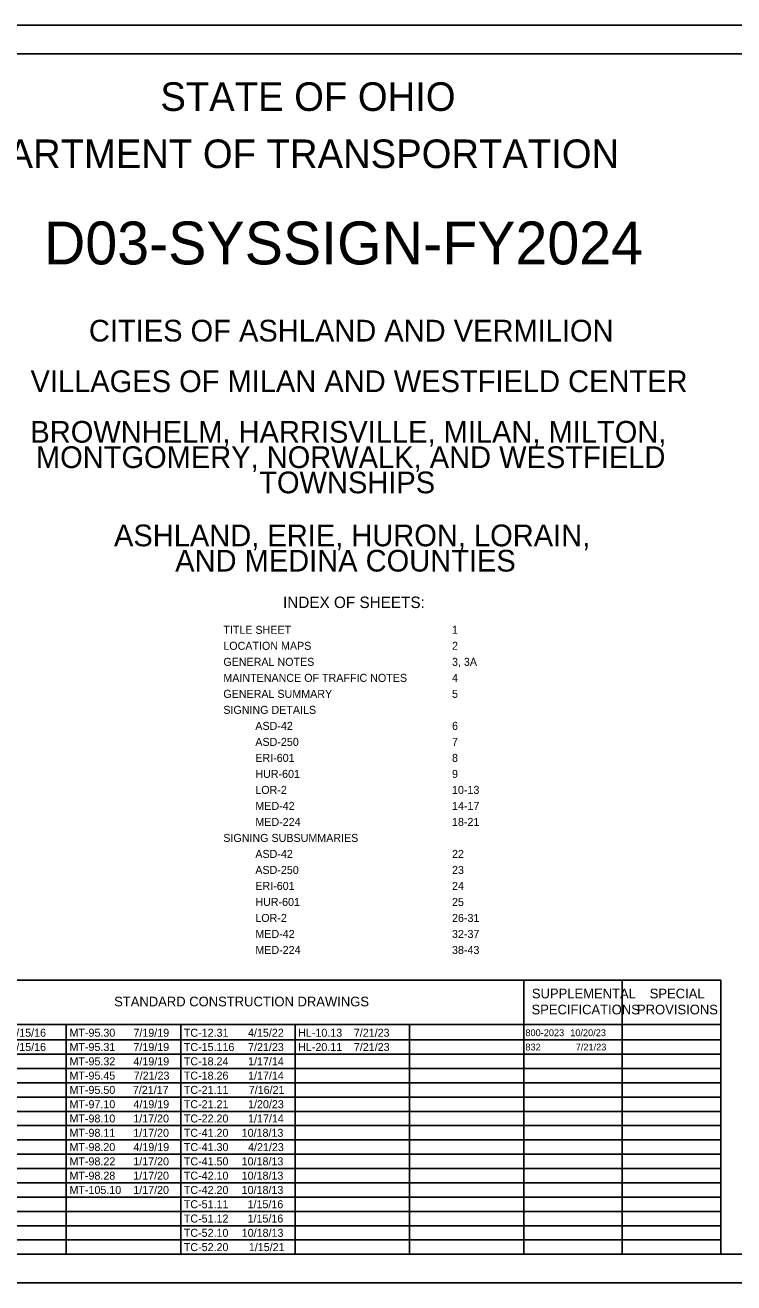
# Model space of a CAD drawing. Extents: x 0 to 34, y 0 to 22.
# Drawn here: x 11.43 to 23.83, y 0 to 22 of the extents above; entities that cross this region are included whole.
import ezdxf

# ---------------------------------------------------------------- set-up
doc = ezdxf.new("R2010")
doc.units = 0
for name, color, linetype in [('SH_Border', 7, 'Continuous'), ('SH_Cut_Line', 7, 'Continuous'), ('SH_Data', 7, 'Continuous'), ('SH_Text', 7, 'Continuous')]:
    doc.layers.add(name, color=color, linetype=linetype)

msp = doc.modelspace()

# ---------------------------------------------------------------- linework, layer by layer
at = {"layer": 'SH_Border'}
msp.add_lwpolyline([(1.5, 21.5), (33.5, 21.5), (33.5, 0.5), (1.5, 0.5)], close=True, dxfattribs=at)
at = {"layer": 'SH_Cut_Line'}
msp.add_lwpolyline([(0, 0), (34, 0), (34, 22), (0, 22)], close=True, dxfattribs=at)
at = {"layer": 'SH_Data'}
for p, q in [((10.15, 5.292), (23.6, 5.292)), ((20.15, 0.5), (20.15, 5.292)), ((21.875, 0.5), (21.875, 5.292)), ((23.6, 0.5), (23.6, 5.292)), ((10.15, 4.521), (23.6, 4.521)), ((12.15, 0.5), (12.15, 4.521)), ((14.15, 0.5), (14.15, 4.521)), ((16.15, 0.5), (16.15, 4.521)), ((18.15, 0.5), (18.15, 4.521)), ((10.15, 4.25), (23.6, 4.25)), ((10.15, 4), (23.6, 4)), ((10.15, 3.75), (23.6, 3.75)), ((10.15, 3.5), (23.6, 3.5)), ((10.15, 3.25), (23.6, 3.25)), ((10.15, 3), (23.6, 3)), ((10.15, 2.75), (23.6, 2.75)), ((10.15, 2.5), (23.6, 2.5)), ((10.15, 2.25), (23.6, 2.25)), ((10.15, 2), (23.6, 2)), ((10.15, 1.75), (23.6, 1.75)), ((10.15, 1.5), (23.6, 1.5)), ((10.15, 1.25), (23.6, 1.25)), ((10.15, 1), (23.6, 1)), ((10.15, 0.75), (23.6, 0.75))]:
    msp.add_line(p, q, dxfattribs=at)

# ---------------------------------------------------------------- texts
at = {"layer": 'SH_Text'}
for s, height, p in [('STATE OF OHIO', 0.5, (13.795, 20.5)), ('DEPARTMENT OF TRANSPORTATION', 0.5, (9.747, 19.5)), ('D03-SYSSIGN-FY2024', 0.75, (11.758, 17.815)), ('CITIES OF ASHLAND AND VERMILION', 0.38, (12.545, 16.466)), ('VILLAGES OF MILAN AND WESTFIELD CENTER', 0.38, (11.524, 15.581)), ('BROWNHELM, HARRISVILLE, MILAN, MILTON,', 0.38, (11.521, 14.696)), ('MONTGOMERY, NORWALK, AND WESTFIELD', 0.38, (11.618, 14.253)), ('TOWNSHIPS', 0.38, (15.524, 13.811)), ('ASHLAND, ERIE, HURON, LORAIN,', 0.38, (12.984, 12.884)), ('AND MEDINA COUNTIES', 0.38, (14.054, 12.442)), ('INDEX OF SHEETS:', 0.2, (15.94, 11.804)), ('TITLE SHEET', 0.14, (14.896, 11.353)), ('1', 0.14, (18.896, 11.353)), ('LOCATION MAPS', 0.14, (14.896, 11.073)), ('2', 0.14, (18.896, 11.073)), ('GENERAL NOTES', 0.14, (14.896, 10.793)), ('3, 3A', 0.14, (18.896, 10.793)), ('MAINTENANCE OF TRAFFIC NOTES', 0.14, (14.896, 10.513)), ('4', 0.14, (18.896, 10.513)), ('GENERAL SUMMARY', 0.14, (14.896, 10.233)), ('5', 0.14, (18.896, 10.233)), ('SIGNING DETAILS', 0.14, (14.896, 9.953)), ('ASD-42', 0.14, (15.456, 9.673)), ('6', 0.14, (18.896, 9.673)), ('ASD-250', 0.14, (15.456, 9.393)), ('7', 0.14, (18.896, 9.393)), ('ERI-601', 0.14, (15.456, 9.113)), ('8', 0.14, (18.896, 9.113)), ('HUR-601', 0.14, (15.456, 8.833)), ('9', 0.14, (18.896, 8.833)), ('LOR-2', 0.14, (15.456, 8.553)), ('10-13', 0.14, (18.896, 8.553)), ('MED-42', 0.14, (15.456, 8.273)), ('14-17', 0.14, (18.896, 8.273)), ('MED-224', 0.14, (15.456, 7.993)), ('18-21', 0.14, (18.896, 7.993)), ('SIGNING SUBSUMMARIES', 0.14, (14.896, 7.713)), ('ASD-42', 0.14, (15.456, 7.433)), ('22', 0.14, (18.896, 7.433)), ('ASD-250', 0.14, (15.456, 7.153)), ('23', 0.14, (18.896, 7.153)), ('ERI-601', 0.14, (15.456, 6.873)), ('24', 0.14, (18.896, 6.873)), ('HUR-601', 0.14, (15.456, 6.593)), ('25', 0.14, (18.896, 6.593)), ('LOR-2', 0.14, (15.456, 6.313)), ('26-31', 0.14, (18.896, 6.313)), ('MED-42', 0.14, (15.456, 6.033)), ('32-37', 0.14, (18.896, 6.033)), ('MED-224', 0.14, (15.456, 5.753)), ('38-43', 0.14, (18.896, 5.753)), ('SUPPLEMENTAL', 0.17, (20.293, 4.976)), ('SPECIAL', 0.17, (22.354, 4.976)), ('STANDARD CONSTRUCTION DRAWINGS', 0.17, (12.986, 4.836)), ('SPECIFICATIONS', 0.17, (20.287, 4.696)), ('PROVISIONS', 0.17, (22.132, 4.696)), ('1/15/16', 0.14, (11.17, 4.305)), ('MT-95.30', 0.14, (12.205, 4.305)), ('7/19/19', 0.14, (13.324, 4.305)), ('TC-12.31', 0.14, (14.205, 4.305)), ('4/15/22', 0.14, (15.328, 4.305)), ('HL-10.13', 0.14, (16.205, 4.305)), ('7/21/23', 0.14, (17.179, 4.305)), ('800-2023', 0.12, (20.18, 4.315)), ('10/20/23', 0.12, (20.964, 4.315)), ('1/15/16', 0.14, (11.17, 4.055)), ('MT-95.31', 0.14, (12.205, 4.055)), ('7/19/19', 0.14, (13.324, 4.055)), ('TC-15.116', 0.14, (14.205, 4.055)), ('7/21/23', 0.14, (15.329, 4.055)), ('HL-20.11', 0.14, (16.205, 4.055)), ('7/21/23', 0.14, (17.179, 4.055)), ('832', 0.12, (20.18, 4.065)), ('7/21/23', 0.12, (21.06, 4.065)), ('MT-95.32', 0.14, (12.205, 3.805)), ('4/19/19', 0.14, (13.324, 3.805)), ('TC-18.24', 0.14, (14.205, 3.805)), ('1/17/14', 0.14, (15.329, 3.805)), ('MT-95.45', 0.14, (12.205, 3.555)), ('7/21/23', 0.14, (13.329, 3.555)), ('TC-18.26', 0.14, (14.205, 3.555)), ('1/17/14', 0.14, (15.329, 3.555)), ('MT-95.50', 0.14, (12.205, 3.305)), ('7/21/17', 0.14, (13.314, 3.305)), ('TC-21.11', 0.14, (14.205, 3.305)), ('7/16/21', 0.14, (15.341, 3.305)), ('MT-97.10', 0.14, (12.205, 3.055)), ('4/19/19', 0.14, (13.324, 3.055)), ('TC-21.21', 0.14, (14.205, 3.055)), ('1/20/23', 0.14, (15.329, 3.055)), ('MT-98.10', 0.14, (12.205, 2.805)), ('1/17/20', 0.14, (13.321, 2.805)), ('TC-22.20', 0.14, (14.205, 2.805)), ('1/17/14', 0.14, (15.329, 2.805)), ('MT-98.11', 0.14, (12.205, 2.555)), ('1/17/20', 0.14, (13.321, 2.555)), ('TC-41.20', 0.14, (14.205, 2.555)), ('10/18/13', 0.14, (15.217, 2.555)), ('MT-98.20', 0.14, (12.205, 2.305)), ('4/19/19', 0.14, (13.324, 2.305)), ('TC-41.30', 0.14, (14.205, 2.305)), ('4/21/23', 0.14, (15.329, 2.305)), ('1/17/20', 0.14, (13.321, 2.055)), ('10/18/13', 0.14, (15.217, 2.055)), ('MT-98.22', 0.14, (12.205, 2.055)), ('TC-41.50', 0.14, (14.205, 2.055)), ('MT-98.28', 0.14, (12.205, 1.805)), ('1/17/20', 0.14, (13.321, 1.805)), ('TC-42.10', 0.14, (14.205, 1.805)), ('10/18/13', 0.14, (15.217, 1.805)), ('MT-105.10', 0.14, (12.205, 1.555)), ('1/17/20', 0.14, (13.321, 1.555)), ('TC-42.20', 0.14, (14.205, 1.555)), ('10/18/13', 0.14, (15.217, 1.555)), ('TC-51.11', 0.14, (14.205, 1.305)), ('1/15/16', 0.14, (15.32, 1.305)), ('TC-51.12', 0.14, (14.205, 1.055)), ('1/15/16', 0.14, (15.32, 1.055)), ('TC-52.10', 0.14, (14.205, 0.805)), ('10/18/13', 0.14, (15.218, 0.805)), ('TC-52.20', 0.14, (14.205, 0.555)), ('1/15/21', 0.14, (15.342, 0.555))]:
    msp.add_text(s, height=height, dxfattribs=at).set_placement(p)

doc.saveas('drawing.dxf')
